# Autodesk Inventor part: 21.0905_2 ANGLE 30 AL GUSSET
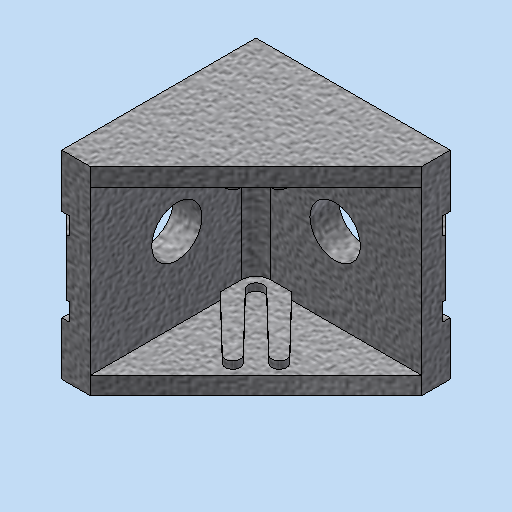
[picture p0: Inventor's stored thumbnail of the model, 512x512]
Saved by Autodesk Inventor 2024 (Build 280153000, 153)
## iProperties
Created: 2017-01
Part Number: 21.0905_2 ANGLE 30 AL GUSSET
Material: Aluminum-6061
Document SubType Name: Modeling
Designer: Admin
Density: 2.7 g/cm^3
Mass: 17.7218 g
Surface Area: 47.3493 cm^2
Volume: 6.56364 cm^3
Appearance: Aluminum Cast
Author: Admin
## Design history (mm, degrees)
feature "Base1"
body "Solid1"
